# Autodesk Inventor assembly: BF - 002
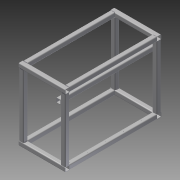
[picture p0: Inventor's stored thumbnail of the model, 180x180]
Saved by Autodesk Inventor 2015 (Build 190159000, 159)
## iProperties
Created: 2007-02
Part Number: BF - 002
Document SubType Name: Weldment
Designer: Autodesk, Inc.
Weld Material: Welded Aluminum-6061
Description: Frame Assembly
Mass: 63576.4 g
Surface Area: 34530 cm^2
Volume: 8112.52 cm^3
Density: 7.83683 g/cm^3
_FrameDoc: Frame Assembly
_Version: 15.0.0
Author: Autodesk, Inc.
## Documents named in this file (15)
- C:\Users\Public\Documents\Autodesk\Inventor 2015\Samples\Models\Assemblies\Blower\Blower\Frame\Blower Frame.iam
- C:\Users\Public\Documents\Autodesk\Inventor 2015\Samples\Models\Assemblies\Blower\Blower\Frame\Skeleton0001.ipt
- C:\Users\Public\Documents\Autodesk\Inventor 2015\Samples\Models\Assemblies\Blower\Blower\Frame\ANSI 2x2x 3_16 00000001.ipt
- C:\Users\Public\Documents\Autodesk\Inventor 2015\Samples\Models\Assemblies\Blower\Blower\Frame\ANSI 2x2x 3_16 00000002.ipt
- C:\Users\Public\Documents\Autodesk\Inventor 2015\Samples\Models\Assemblies\Blower\Blower\Frame\ANSI 2x2x 3_16 00000003.ipt
- C:\Users\Public\Documents\Autodesk\Inventor 2015\Samples\Models\Assemblies\Blower\Blower\Frame\ANSI 2x2x 3_16 00000004.ipt
- C:\Users\Public\Documents\Autodesk\Inventor 2015\Samples\Models\Assemblies\Blower\Blower\Frame\ANSI 2x2x 3_16 00000005.ipt
- C:\Users\Public\Documents\Autodesk\Inventor 2015\Samples\Models\Assemblies\Blower\Blower\Frame\ANSI 2x2x 3_16 00000006.ipt
- C:\Users\Public\Documents\Autodesk\Inventor 2015\Samples\Models\Assemblies\Blower\Blower\Frame\ANSI 2x2x 3_16 00000007.ipt
- C:\Users\Public\Documents\Autodesk\Inventor 2015\Samples\Models\Assemblies\Blower\Blower\Frame\ANSI 2x2x 3_16 00000008.ipt
- C:\Users\Public\Documents\Autodesk\Inventor 2015\Samples\Models\Assemblies\Blower\Blower\Frame\ANSI 2x2x 3_16 00000009.ipt
- C:\Users\Public\Documents\Autodesk\Inventor 2015\Samples\Models\Assemblies\Blower\Blower\Frame\ANSI 2x2x 3_16 00000010.ipt
- C:\Users\Public\Documents\Autodesk\Inventor 2015\Samples\Models\Assemblies\Blower\Blower\Frame\ANSI 2x2x 3_16 00000011.ipt
- C:\Users\Public\Documents\Autodesk\Inventor 2015\Samples\Models\Assemblies\Blower\Blower\Frame\ANSI 2x2x 3_16 00000012.ipt
- C:\Users\Public\Documents\Autodesk\Inventor 2015\Samples\Models\Assemblies\Blower\Blower\Frame\ANSI 2x2x 3_16 00000013.ipt
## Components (14 placed, 14 different names)
1. Skeleton0001:2
2. ANSI 2x2x 3_16 00000001:3
3. ANSI 2x2x 3_16 00000002:4
4. ANSI 2x2x 3_16 00000003:5
5. ANSI 2x2x 3_16 00000004:6
6. ANSI 2x2x 3_16 00000005:7
7. ANSI 2x2x 3_16 00000006:8
8. ANSI 2x2x 3_16 00000007:9
9. ANSI 2x2x 3_16 00000008:10
10. ANSI 2x2x 3_16 00000009:11
11. ANSI 2x2x 3_16 00000010:12
12. ANSI 2x2x 3_16 00000011:13
13. ANSI 2x2x 3_16 00000012:14
14. ANSI 2x2x 3_16 00000013:15
